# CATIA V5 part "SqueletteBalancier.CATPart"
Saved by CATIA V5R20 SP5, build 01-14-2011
Part number: SqueletteBalancier
Publications: "Droite.1", "Droite.2"
Bounding box of the stored display mesh (mm): x 0 to 0, y 0 to 220, z -30 to 100
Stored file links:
  F:\IAO_bmadec\bmadecf\SqueletteBalancier.CATPart
  F:\IAO_bmadec\bmadecf\squelette.CATProduct
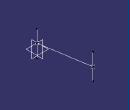
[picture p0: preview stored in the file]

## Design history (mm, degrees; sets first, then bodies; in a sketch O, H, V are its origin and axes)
Set1
  Plane1: linked copy from another document
  Point1: linked copy from another document
  Point2: linked copy from another document
Set2
  Line1: type Normal, RefPoint Point1, RefSkin Plane1, Start -50, End 50
  Line2: type Normal, RefPoint Point2, RefSkin Plane1, Start -50, End 50
  Line3: type PtPt, FirstPoint Point1, SecondPoint Point2
Body1 (main body)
